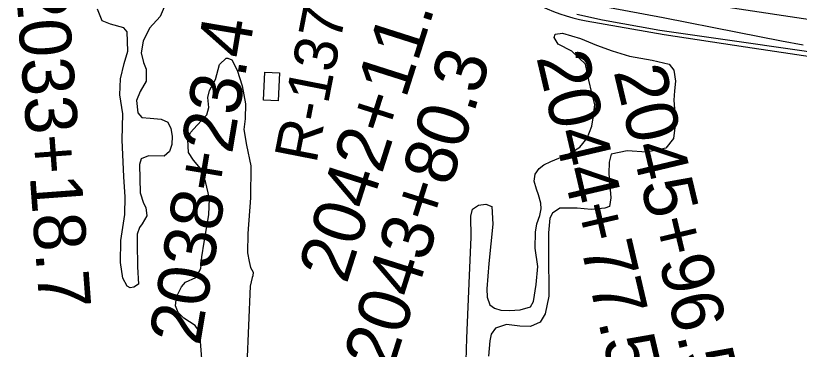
# Model space of a CAD drawing. Extents: x 3508733 to 3546731, y 546897 to 572481.
# Drawn here: x 3527074 to 3528588, y 561726 to 562371 of the extents above; entities that cross this region are included whole.
import ezdxf

# ---------------------------------------------------------------- set-up
doc = ezdxf.new("R2010")
doc.units = 0
for name, color, linetype in [('V-BLDG-OTLN', 7, 'Continuous'), ('V-LEVE-TOET', 7, 'Continuous'), ('V-RIVR-RANG-IDEN', 7, 'Continuous'), ('V-ROAD-CNTR', 7, 'Continuous'), ('V-SITE-VEGE', 7, 'Continuous'), ('V-SURV-IDEN', 7, 'Continuous'), ('V-SURV-LINE', 7, 'Continuous'), ('V-TOPO-SHOR', 7, 'Continuous')]:
    doc.layers.add(name, color=color, linetype=linetype)

msp = doc.modelspace()

# ---------------------------------------------------------------- linework, layer by layer
at = {"layer": 'V-BLDG-OTLN'}
msp.add_lwpolyline([(3527583.4, 562260.2), (3527580.8, 562206.2), (3527552.7, 562207.6), (3527555.3, 562261.6)], close=True, dxfattribs=at)
at = {"layer": 'V-LEVE-TOET'}
msp.add_lwpolyline([(3528594.8, 562313.7), (3528553.1, 562321.6), (3528468.3, 562338.3), (3528324.7, 562366.4), (3528183.1, 562393.2)], dxfattribs=at)
at = {"layer": 'V-ROAD-CNTR'}
msp.add_lwpolyline([(3530757.8, 561962.6), (3530375.4, 562015.6), (3529917.2, 562082.3), (3529550.4, 562141.6), (3529261.2, 562190.2), (3528940.5, 562241.7), (3528483.4, 562310), (3528326.5, 562333.9), (3528176, 562360.4)], dxfattribs=at)
msp.add_arc((3528248, 562728.4), 374.9, 226.6592, 258.9323, dxfattribs=at)
at = {"layer": 'V-SITE-VEGE'}
for points in [[(3527361, 562386.9), (3527353.3, 562369.2), (3527332.5, 562346.8), (3527319.9, 562321.6), (3527316.3, 562299), (3527320.9, 562280.4), (3527326.2, 562267.4), (3527326, 562244.1), (3527314.2, 562224.3), (3527307.1, 562206.6), (3527309.6, 562183.3), (3527317.8, 562174.3), (3527333.5, 562172.7), (3527354.7, 562171.1), (3527367.7, 562164.8), (3527373.7, 562153.1), (3527376.3, 562138), (3527375.5, 562121.6), (3527371.2, 562108.6), (3527360.8, 562099.1), (3527330.7, 562100.1), (3527316.3, 562094.1), (3527313.4, 562083.2), (3527314.2, 562028.3), (3527320.9, 562008.4), (3527325.6, 562000.1), (3527327.5, 561984.3), (3527318.4, 561968.7), (3527312.9, 561961.9), (3527308.6, 561948.9), (3527308.4, 561931.8), (3527309.3, 561885.9), (3527311.1, 561852.3), (3527302.1, 561846.2), (3527295.2, 561844.9), (3527289.1, 561848.4), (3527281, 561863.5), (3527276.5, 561893.7), (3527277, 561936.2), (3527285, 561986.8), (3527285.4, 562021.1), (3527283, 562059.5), (3527279.6, 562130.8), (3527280.8, 562180.8), (3527275, 562217.9), (3527276.7, 562248.7), (3527283.2, 562278.1), (3527290.3, 562302), (3527289.3, 562339.7), (3527282.5, 562347.3), (3527257.2, 562354.4), (3527240.9, 562360.7), (3527232.2, 562383.5)], [(3527944.1, 561704), (3527945.2, 561747.8), (3527950.6, 561869.1), (3527953.4, 561943), (3527953.1, 561983.5), (3527956, 561997.1), (3527967.7, 562004.6), (3527982.1, 562006.5), (3527993.7, 562002.2), (3527995.4, 561968), (3527987.8, 561892), (3527983.9, 561843.4), (3527984.4, 561826.9), (3527989.7, 561812.5), (3527998.6, 561805.5), (3528010.9, 561802), (3528028, 561801.1), (3528048.6, 561802.3), (3528068.5, 561808.2), (3528074.1, 561818.5), (3528079.2, 561851.3), (3528082.3, 561886.2), (3528077.2, 561921.9), (3528078.2, 561952.7), (3528080.4, 561968.5), (3528086.1, 561984.9), (3528088.9, 561997.8), (3528088.4, 562008.8), (3528083.7, 562024.6), (3528079.7, 562035.6), (3528075.1, 562051.4), (3528077.3, 562064.4), (3528084.9, 562075.3), (3528093.9, 562082.8), (3528107.7, 562088.8), (3528141.4, 562103.5), (3528163.5, 562117), (3528178, 562134), (3528186.5, 562157.2), (3528190.1, 562177), (3528192.4, 562198.9), (3528186.5, 562221.6), (3528181.2, 562246.3), (3528174.7, 562277.2), (3528148.2, 562302.2), (3528121.6, 562315.5), (3528114.2, 562328.6), (3528115.7, 562334.7), (3528130.1, 562336.6), (3528164.9, 562326.7), (3528195.6, 562314), (3528226.3, 562302.8), (3528259.8, 562292.8), (3528303.6, 562284.8), (3528336.4, 562277), (3528345.2, 562265.2), (3528348.4, 562244), (3528346.2, 562225.5), (3528345.3, 562207.7), (3528348.3, 562165.1), (3528344.5, 562133.7), (3528330, 562114.6), (3528292.9, 562106.8), (3528255.2, 562109.9), (3528224.3, 562103.4), (3528220, 562087.7), (3528219.8, 562065.7), (3528223.5, 562019.1), (3528221.2, 562002), (3528211.6, 561998.7), (3528185.5, 561996.2), (3528158.2, 561999.2), (3528125.3, 561998.8), (3528110.8, 561989.4), (3528105.9, 561979.9), (3528102.8, 561951.1), (3528103.2, 561914.1), (3528103.7, 561829.1), (3528096.5, 561794.9), (3528086.7, 561778.6), (3528068.1, 561770.6), (3528047.6, 561770.8), (3528022.2, 561774.4), (3528000.9, 561767.1), (3527992.6, 561755.6), (3527989.7, 561742.6), (3527987.4, 561713.1)], [(3527435.4, 561683.1), (3527431.2, 561741.4), (3527428, 561762), (3527420.6, 561772.3), (3527398.8, 561786.3), (3527387.9, 561797.3), (3527382.6, 561810.4), (3527384.8, 561827.5), (3527393.9, 561847.3), (3527402.2, 561856.1), (3527422.2, 561864.8), (3527431.3, 561882.6), (3527433.6, 561905.2), (3527438, 561933.2), (3527446.7, 561985.9), (3527448.4, 562017.4), (3527440.5, 562050.4), (3527431.2, 562075.8), (3527417.6, 562091.7), (3527407.5, 562106.2), (3527406.4, 562131.6), (3527411.3, 562145.2), (3527424.5, 562159.5), (3527443.2, 562179.2), (3527446.8, 562193.5), (3527444.9, 562212.7), (3527448.5, 562226.4), (3527459.7, 562247.5), (3527467.5, 562276.2), (3527480.6, 562288.4), (3527483.4, 562288.4), (3527491.6, 562285.6), (3527501.6, 562265.6), (3527511.6, 562235.3), (3527518.1, 562200.3), (3527517.1, 562171.6), (3527514.9, 562151), (3527520, 562120.8), (3527527.9, 562081), (3527527.2, 562018.6), (3527522.4, 561950.2), (3527522, 561912.5), (3527524.6, 561896), (3527527.2, 561884.3), (3527532.6, 561875.4), (3527531.9, 561868.5), (3527530.5, 561865.1), (3527526.9, 561848), (3527520.5, 561696.6)]]:
    msp.add_lwpolyline(points, dxfattribs=at)
at = {"layer": 'V-SURV-LINE'}
msp.add_lwpolyline([(3530782, 562035.8), (3528219, 562422)], dxfattribs=at)
at = {"layer": 'V-TOPO-SHOR'}
msp.add_lwpolyline([(3528157.7, 562373.8), (3528207.5, 562362.4), (3528318, 562342.8), (3528475.6, 562320), (3528641.4, 562296.5)], dxfattribs=at)

# ---------------------------------------------------------------- texts
at = {"layer": 'V-RIVR-RANG-IDEN'}
msp.add_text('R-137.6', height=83, rotation=78.9114, dxfattribs=at).set_placement((3527654.5, 562083.3))
at = {"layer": 'V-SURV-IDEN'}
for s, rotation, p in [('2042+11.4', 72.2913, (3527713.1, 561850.8)), ('2033+18.7', 274.2332, (3527073.4, 562435.6)), ('2038+23.4', 80.4803, (3527429.7, 561731.5)), ('2043+80.3', 72.4497, (3527800.3, 561680.3)), ('2044+77.5', 283.173, (3528079.3, 562290.6)), ('2045+96.5', 283.4587, (3528228.4, 562263.2))]:
    msp.add_text(s, height=100, rotation=rotation, dxfattribs=at).set_placement(p)

doc.saveas('drawing.dxf')
